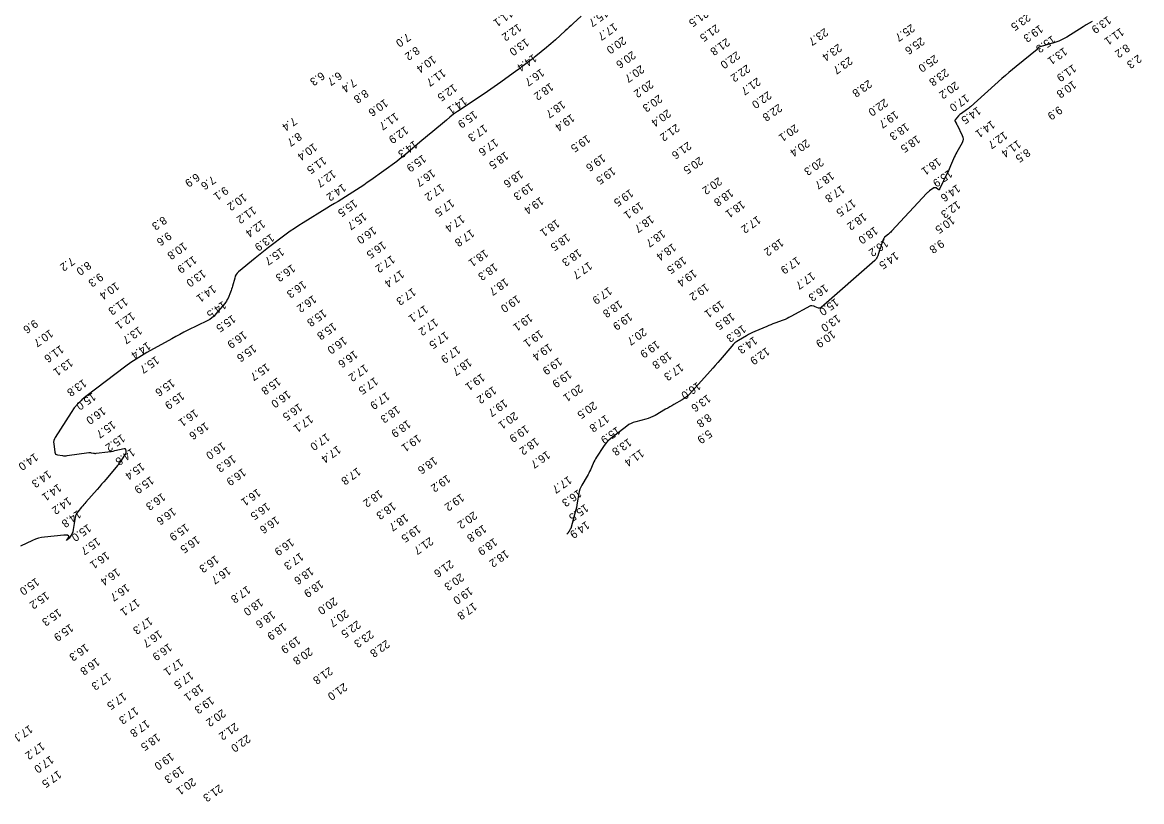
# Model space of a CAD drawing. Extents: x 988130 to 1132882, y 654656 to 841453.
# Drawn here: x 1035801 to 1036500, y 779520 to 780006 of the extents above; entities that cross this region are included whole.
import ezdxf

# ---------------------------------------------------------------- set-up
doc = ezdxf.new("R2010")
doc.units = 0
doc.layers.add('V-TOPO-MAJR', color=7, linetype='Continuous')
doc.layers.add('V-TOPO-SOUN', color=7, linetype='Continuous')

msp = doc.modelspace()

# ---------------------------------------------------------------- linework, layer by layer
at = {"layer": 'V-TOPO-MAJR'}
for points in [[(1036149.85, 780010.24), (1036144.84, 780005.7), (1036143.59, 780004.56), (1036142.34, 780003.42), (1036141.09, 780002.28), (1036139.85, 780001.14), (1036133.83, 779995.59), (1036132.46, 779994.35), (1036131.07, 779993.13), (1036129.66, 779991.93), (1036128.24, 779990.75), (1036121.56, 779985.29), (1036120.59, 779984.52), (1036119.62, 779983.75), (1036118.65, 779983), (1036117.66, 779982.26), (1036113.7, 779979.31), (1036112.7, 779978.57), (1036111.71, 779977.84), (1036110.72, 779977.1), (1036109.72, 779976.37), (1036099.66, 779969), (1036097.64, 779967.54), (1036095.61, 779966.1), (1036093.56, 779964.69), (1036091.49, 779963.3), (1036074.93, 779952.33), (1036072.54, 779950.71), (1036070.21, 779949.02), (1036067.92, 779947.27), (1036065.68, 779945.45), (1036055.92, 779937.31), (1036054.16, 779935.83), (1036052.39, 779934.35), (1036050.63, 779932.86), (1036048.88, 779931.36), (1036041.87, 779925.36), (1036040.11, 779923.88), (1036038.31, 779922.43), (1036036.49, 779921.02), (1036034.64, 779919.65), (1036018.49, 779907.94), (1036016.27, 779906.36), (1036014.04, 779904.83), (1036011.77, 779903.33), (1036009.48, 779901.86), (1036000.28, 779896.09), (1035997.97, 779894.65), (1035995.67, 779893.22), (1035993.35, 779891.79), (1035991.04, 779890.37), (1035976.13, 779881.26), (1035973.43, 779879.56), (1035970.77, 779877.8), (1035968.16, 779875.99), (1035965.58, 779874.11), (1035954.48, 779865.82), (1035952.37, 779864.22), (1035950.28, 779862.6), (1035948.22, 779860.94), (1035946.18, 779859.26), (1035935.86, 779850.61), (1035935.01, 779849.8), (1035934.32, 779848.88), (1035933.79, 779847.87), (1035933.4, 779846.77), (1035932.07, 779841.79), (1035931.79, 779840.82), (1035931.48, 779839.85), (1035931.14, 779838.9), (1035930.76, 779837.96), (1035929.21, 779834.21), (1035928.79, 779833.29), (1035928.3, 779832.41), (1035927.75, 779831.58), (1035927.13, 779830.78), (1035921.66, 779824.32), (1035920.47, 779823.05), (1035919.18, 779821.93), (1035917.77, 779820.95), (1035916.26, 779820.11), (1035904.09, 779814.15), (1035901.55, 779812.88), (1035899.02, 779811.58), (1035896.51, 779810.24), (1035894.02, 779808.87), (1035878.49, 779800.19), (1035875.11, 779798.22), (1035871.8, 779796.15), (1035868.57, 779793.96), (1035865.41, 779791.67), (1035840.45, 779772.89), (1035837.8, 779770.71), (1035835.37, 779768.31), (1035833.17, 779765.71), (1035831.19, 779762.9), (1035821.2, 779747.29), (1035820.69, 779746.33), (1035820.36, 779745.32), (1035820.23, 779744.27), (1035820.28, 779743.19), (1035820.94, 779738.06), (1035821.12, 779737.38), (1035821.47, 779736.86), (1035821.99, 779736.51), (1035822.67, 779736.33), (1035825.73, 779735.92), (1035826.49, 779735.84), (1035827.25, 779735.81), (1035828.02, 779735.84), (1035828.78, 779735.92), (1035842.19, 779737.72), (1035842.57, 779737.76), (1035842.94, 779737.76), (1035843.32, 779737.74), (1035843.7, 779737.68), (1035845.21, 779737.37), (1035845.58, 779737.31), (1035845.96, 779737.28), (1035846.34, 779737.28), (1035846.72, 779737.31), (1035854.07, 779738.21), (1035855.18, 779738.35), (1035856.28, 779738.53), (1035857.38, 779738.74), (1035858.47, 779738.98), (1035864.37, 779740.33), (1035864.66, 779740.35), (1035864.89, 779740.28), (1035865.04, 779740.1), (1035865.13, 779739.82), (1035865.36, 779738.5), (1035865.39, 779738.17), (1035865.36, 779737.86), (1035865.27, 779737.56), (1035865.13, 779737.26), (1035862.44, 779732.79), (1035861.92, 779731.96), (1035861.36, 779731.15), (1035860.77, 779730.37), (1035860.16, 779729.61), (1035852.98, 779721.16), (1035851.6, 779719.55), (1035850.22, 779717.95), (1035848.83, 779716.35), (1035847.43, 779714.77), (1035840.3, 779706.73), (1035839.65, 779705.99), (1035839.01, 779705.25), (1035838.38, 779704.5), (1035837.75, 779703.74), (1035835.26, 779700.7), (1035834.7, 779699.91), (1035834.25, 779699.07), (1035833.92, 779698.18), (1035833.71, 779697.24), (1035832.53, 779689.8), (1035832.18, 779688.3), (1035831.61, 779686.89), (1035830.83, 779685.6), (1035829.84, 779684.41), (1035828.3, 779682.81), (1035829.6, 779684.47), (1035829.77, 779685.58), (1035828.8, 779686.14), (1035826.69, 779686.15), (1035814.48, 779684.93), (1035812.58, 779684.66), (1035810.72, 779684.23), (1035808.9, 779683.65), (1035807.13, 779682.91), (1035799.53, 779679.34)], [(1036469.38, 780006.98), (1036467.48, 780005.92), (1036465.61, 780004.82), (1036463.75, 780003.68), (1036453.43, 779997.23), (1036451.8, 779996.28), (1036450.11, 779995.45), (1036448.38, 779994.72), (1036446.59, 779994.12), (1036436, 779990.89), (1036435.87, 779990.84), (1036435.75, 779990.76), (1036435.66, 779990.66), (1036435.59, 779990.54), (1036435.32, 779990.02), (1036435.25, 779989.89), (1036435.17, 779989.77), (1036435.07, 779989.66), (1036434.96, 779989.57), (1036421.71, 779978.8), (1036419.48, 779976.96), (1036417.27, 779975.1), (1036415.08, 779973.2), (1036412.91, 779971.29), (1036393.35, 779953.79), (1036392.72, 779953.25), (1036392.08, 779952.72), (1036391.41, 779952.22), (1036390.73, 779951.74), (1036387.63, 779949.62), (1036387.13, 779949.25), (1036386.65, 779948.85), (1036386.2, 779948.43), (1036385.78, 779947.97), (1036383.74, 779945.61), (1036383.57, 779945.36), (1036383.5, 779945.11), (1036383.53, 779944.85), (1036383.64, 779944.58), (1036384.28, 779943.48), (1036384.44, 779943.2), (1036384.59, 779942.92), (1036384.74, 779942.64), (1036384.88, 779942.36), (1036388.11, 779935.86), (1036388.54, 779934.69), (1036388.66, 779933.53), (1036388.48, 779932.37), (1036387.98, 779931.22), (1036384.71, 779925.44), (1036384.15, 779924.41), (1036383.62, 779923.36), (1036383.12, 779922.31), (1036382.66, 779921.23), (1036380.85, 779916.91), (1036380.39, 779915.83), (1036379.92, 779914.76), (1036379.43, 779913.69), (1036378.93, 779912.63), (1036373.95, 779902.25), (1036373.79, 779902.01), (1036373.6, 779901.9), (1036373.38, 779901.91), (1036373.13, 779902.03), (1036371.74, 779903.01), (1036371.63, 779903.07), (1036371.52, 779903.12), (1036371.4, 779903.15), (1036371.28, 779903.16), (1036370.77, 779903.17), (1036370.64, 779903.17), (1036370.52, 779903.14), (1036370.41, 779903.1), (1036370.3, 779903.03), (1036367.63, 779901.2), (1036367.16, 779900.86), (1036366.71, 779900.49), (1036366.29, 779900.1), (1036365.88, 779899.69), (1036343.8, 779875.98), (1036343.36, 779875.52), (1036342.91, 779875.08), (1036342.45, 779874.66), (1036341.97, 779874.25), (1036340.04, 779872.63), (1036339.59, 779872.2), (1036339.21, 779871.73), (1036338.89, 779871.2), (1036338.64, 779870.64), (1036337.43, 779867.27), (1036337.16, 779866.51), (1036336.9, 779865.74), (1036336.65, 779864.98), (1036336.4, 779864.21), (1036335.31, 779860.69), (1036334.99, 779859.87), (1036334.58, 779859.13), (1036334.07, 779858.45), (1036333.45, 779857.83), (1036299.96, 779828.32), (1036299.59, 779828.07), (1036299.2, 779827.93), (1036298.78, 779827.92), (1036298.35, 779828.04), (1036296.14, 779828.89), (1036295.9, 779828.98), (1036295.66, 779829.06), (1036295.42, 779829.13), (1036295.17, 779829.2), (1036294.18, 779829.45), (1036293.94, 779829.49), (1036293.7, 779829.48), (1036293.47, 779829.43), (1036293.24, 779829.33), (1036281, 779822.7), (1036279.8, 779822.08), (1036278.58, 779821.5), (1036277.35, 779820.96), (1036276.09, 779820.46), (1036271.02, 779818.56), (1036269.75, 779818.08), (1036268.49, 779817.58), (1036267.24, 779817.07), (1036265.99, 779816.55), (1036258.39, 779813.29), (1036257.08, 779812.71), (1036255.8, 779812.08), (1036254.53, 779811.42), (1036253.28, 779810.72), (1036248.33, 779807.84), (1036247.13, 779807.07), (1036246.01, 779806.21), (1036244.97, 779805.26), (1036244, 779804.21), (1036236.8, 779795.72), (1036235.28, 779793.95), (1036233.75, 779792.19), (1036232.2, 779790.44), (1036230.64, 779788.71), (1036217.61, 779774.35), (1036216.58, 779773.3), (1036215.47, 779772.34), (1036214.29, 779771.47), (1036213.04, 779770.69), (1036207.88, 779767.76), (1036206.59, 779767.03), (1036205.3, 779766.29), (1036204.01, 779765.55), (1036202.73, 779764.81), (1036196.15, 779761.02), (1036194.74, 779760.27), (1036193.29, 779759.62), (1036191.8, 779759.08), (1036190.27, 779758.63), (1036184.05, 779757.06), (1036182.53, 779756.59), (1036181.08, 779755.98), (1036179.71, 779755.21), (1036178.41, 779754.3), (1036168.45, 779746.52), (1036167.16, 779745.42), (1036165.96, 779744.23), (1036164.88, 779742.94), (1036163.89, 779741.56), (1036159.49, 779734.82), (1036158.91, 779733.89), (1036158.37, 779732.94), (1036157.87, 779731.96), (1036157.42, 779730.96), (1036155.67, 779726.93), (1036155.21, 779725.93), (1036154.73, 779724.95), (1036154.21, 779723.98), (1036153.66, 779723.03), (1036150.35, 779717.47), (1036149.68, 779716.21), (1036149.13, 779714.9), (1036148.71, 779713.54), (1036148.43, 779712.14), (1036147.52, 779706.3), (1036147.27, 779704.86), (1036146.98, 779703.42), (1036146.64, 779702), (1036146.26, 779700.58), (1036143.38, 779690.44), (1036143.36, 779690.39), (1036143.34, 779690.34), (1036143.31, 779690.29), (1036143.28, 779690.25), (1036143.16, 779690.06), (1036143.13, 779690.02), (1036143.1, 779689.97), (1036143.07, 779689.92), (1036143.04, 779689.88), (1036142.12, 779688.34), (1036142.02, 779688.18), (1036141.92, 779688.02), (1036141.81, 779687.86), (1036141.7, 779687.71), (1036141.02, 779686.81)]]:
    msp.add_lwpolyline(points, dxfattribs=at)

# ---------------------------------------------------------------- texts
at = {"layer": 'V-TOPO-SOUN'}
for s, p in [('11.1 ', (1036105.2, 780014.76)), ('15.7 ', (1036164.73, 780014.81)), ('21.5 ', (1036227.36, 780014.72)), ('23.5 ', (1036428.64, 780012.32)), ('13.9 ', (1036479.03, 780010.63)), ('12.2 ', (1036110.48, 780005.91)), ('17.7 ', (1036170.43, 780006.32)), ('21.5 ', (1036234.21, 780005.47)), ('23.7 ', (1036302.11, 780003.08)), ('25.7 ', (1036356.25, 780005.64)), ('19.3 ', (1036436.49, 780005.12)), ('11.1 ', (1036487.05, 780003.29)), ('7.0', (1036041.2, 779999.98)), ('13.0 ', (1036115.23, 779996.71)), ('20.0 ', (1036175.94, 779997.87)), ('21.8 ', (1036240.7, 779996.83)), ('23.4 ', (1036310.69, 779993.33)), ('25.6 ', (1036362.42, 779997.43)), ('15.3 ', (1036444.28, 779998.51)), ('8.2', (1036046.81, 779991.68)), ('14.4 ', (1036120.04, 779986.89)), ('20.6 ', (1036181.87, 779988.78)), ('22.0 ', (1036247.08, 779988.59)), ('25.0 ', (1036370.8, 779986.43)), ('13.1 ', (1036451.59, 779991.06)), ('8.2', (1036490.61, 779993.26)), ('2.3', (1036498.04, 779986.54)), ('10.4 ', (1036057.13, 779985.97)), ('20.7 ', (1036187.23, 779980.01)), ('22.2 ', (1036253.48, 779980.33)), ('23.7 ', (1036317.38, 779985.24)), ('11.9 ', (1036457.23, 779980.48)), ('6.3', (1035987.52, 779975.85)), ('6.7', (1035998.29, 779975.92)), ('11.7 ', (1036063.19, 779977.58)), ('16.7 ', (1036124.77, 779977.81)), ('23.8 ', (1036377.5, 779977.78)), ('7.4', (1036007.32, 779971.62)), ('12.5 ', (1036070.22, 779968.24)), ('18.2 ', (1036130.52, 779968.91)), ('20.2 ', (1036192.98, 779970.54)), ('21.7 ', (1036259.94, 779972.18)), ('23.8 ', (1036329.5, 779970.81)), ('20.2 ', (1036383.8, 779969.74)), ('10.8 ', (1036457.21, 779970.28)), ('8.8', (1036014.88, 779964.88)), ('10.6 ', (1036027.09, 779958.82)), ('14.1 ', (1036076.41, 779960.14)), ('20.3 ', (1036198.51, 779961.52)), ('22.0 ', (1036266.73, 779963.7)), ('22.0 ', (1036339.51, 779958.99)), ('17.0 ', (1036390.31, 779961.82)), ('15.9 ', (1036082.94, 779951.53)), ('18.7 ', (1036137.94, 779957.81)), ('20.4 ', (1036203.87, 779952.34)), ('22.8 ', (1036273.39, 779955.79)), ('19.7 ', (1036346.1, 779951.45)), ('14.5 ', (1036397.62, 779954.05)), ('9.9', (1036448.49, 779954.45)), ('7.4', (1035970.12, 779947.53)), ('11.7 ', (1036033.74, 779950.32)), ('19.4 ', (1036143.75, 779949.47)), ('14.1 ', (1036406.42, 779945.45)), ('8.7', (1035973.14, 779937.94)), ('12.9 ', (1036039.79, 779941.85)), ('17.3 ', (1036089.32, 779943.01)), ('21.2 ', (1036209.34, 779943.3)), ('20.1 ', (1036283.56, 779943.06)), ('18.3 ', (1036352.79, 779943.89)), ('12.7 ', (1036414.26, 779938.6)), ('10.4 ', (1035982.75, 779931.26)), ('14.3 ', (1036045.61, 779932.9)), ('17.6 ', (1036095.97, 779934.14)), ('19.5 ', (1036153.54, 779936.41)), ('21.6 ', (1036216.67, 779932.12)), ('20.4 ', (1036290.6, 779933.66)), ('18.5 ', (1036359.7, 779936.17)), ('11.4 ', (1036422.69, 779933.18)), ('15.9 ', (1036050.91, 779924.1)), ('18.5 ', (1036102.45, 779925.92)), ('19.6 ', (1036163.06, 779924.38)), ('8.5', (1036428.5, 779927.89)), ('11.5 ', (1035988.62, 779922.84)), ('20.5 ', (1036223.94, 779922.76)), ('20.3 ', (1036299.39, 779921.93)), ('18.1 ', (1036372.72, 779922.12)), ('6.9', (1035909.38, 779912.55)), ('7.6', (1035919.38, 779910.83)), ('12.7 ', (1035994.54, 779914.54)), ('16.7 ', (1036056.63, 779914.98)), ('18.6 ', (1036111.61, 779914.26)), ('19.5 ', (1036169.36, 779916.3)), ('20.2 ', (1036235.78, 779910.01)), ('18.7 ', (1036305.96, 779913.39)), ('15.9 ', (1036379.82, 779914.72)), ('9.1', (1035927.28, 779904.17)), ('14.2 ', (1036000.87, 779905.96)), ('17.2 ', (1036062.3, 779905.95)), ('19.3 ', (1036117.81, 779906.38)), ('19.5 ', (1036180.44, 779902.55)), ('18.8 ', (1036243.01, 779902.65)), ('17.8 ', (1036312.5, 779904.99)), ('14.6 ', (1036384.74, 779905.52)), ('10.2 ', (1035938.84, 779899.93)), ('15.5 ', (1036007.96, 779896.11)), ('17.5 ', (1036068.56, 779896.29)), ('19.4 ', (1036124.4, 779897.66)), ('17.5 ', (1036319.46, 779896.23)), ('11.2 ', (1035944.7, 779891.81)), ('19.1 ', (1036186.72, 779894.64)), ('18.1 ', (1036250.2, 779895.43)), ('12.3 ', (1036384.9, 779895.22)), ('8.3', (1035888.77, 779885.65)), ('12.4 ', (1035950.36, 779883.36)), ('15.7 ', (1036013.82, 779887.96)), ('17.4 ', (1036075.07, 779886.37)), ('18.1 ', (1036134.38, 779883.62)), ('18.7 ', (1036193.32, 779886.22)), ('17.2 ', (1036260.05, 779885.85)), ('18.2 ', (1036326.24, 779887.74)), ('10.5 ', (1036381.33, 779885.61)), ('9.6', (1035891.73, 779875.85)), ('13.9 ', (1035956.01, 779874.7)), ('16.0 ', (1036019.85, 779879.17)), ('17.8 ', (1036081.07, 779877.5)), ('18.5 ', (1036140.9, 779874.79)), ('18.7 ', (1036200.46, 779877.14)), ('18.0 ', (1036333.28, 779879.17)), ('10.8 ', (1035901.46, 779869.39)), ('16.5 ', (1036025.92, 779870.02)), ('18.4 ', (1036207.13, 779868.69)), ('18.2 ', (1036274.37, 779871.65)), ('16.2 ', (1036339.8, 779871.3)), ('9.8', (1036374.64, 779871.06)), ('11.9 ', (1035907.54, 779860.85)), ('15.7 ', (1035962.21, 779865.94)), ('17.2 ', (1036031.42, 779861.19)), ('18.1 ', (1036089.69, 779864.89)), ('18.3 ', (1036148.11, 779865.21)), ('14.5 ', (1036346.23, 779863.35)), ('7.2', (1035831.29, 779860.01)), ('8.0', (1035841.54, 779857.43)), ('16.3 ', (1035969.14, 779855.59)), ('18.3 ', (1036095.66, 779856.33)), ('17.7 ', (1036154.68, 779857.2)), ('18.5 ', (1036213.65, 779860.44)), ('17.9 ', (1036284.7, 779860.38)), ('9.3', (1035849.06, 779850.19)), ('13.0 ', (1035913.28, 779852.3)), ('17.4 ', (1036037.17, 779851.97)), ('18.7 ', (1036102.47, 779847)), ('19.4 ', (1036220.08, 779852.39)), ('17.7 ', (1036294.01, 779850.79)), ('10.4 ', (1035859.06, 779844.44)), ('14.1 ', (1035919.63, 779842.69)), ('16.3 ', (1035976.07, 779845.38)), ('17.3 ', (1036044.54, 779840.87)), ('17.9 ', (1036167.07, 779841.48)), ('19.2 ', (1036227.72, 779843.7)), ('16.3 ', (1036302.15, 779843.21)), ('11.3 ', (1035864.55, 779834.77)), ('14.5 ', (1035926.02, 779832.65)), ('16.2 ', (1035982.37, 779836.34)), ('19.0 ', (1036109.78, 779836.35)), ('18.8 ', (1036173.59, 779833.16)), ('19.1 ', (1036237.12, 779832.97)), ('15.0 ', (1036308.8, 779834.38)), ('12.1 ', (1035868.97, 779825.79)), ('15.8 ', (1035988.74, 779827.52)), ('17.1 ', (1036052.16, 779830.06)), ('9.6', (1035808.29, 779821.09)), ('15.5 ', (1035931.9, 779824.02)), ('15.8 ', (1035994.96, 779819.23)), ('17.2 ', (1036058.42, 779821.85)), ('19.1 ', (1036117.54, 779824.61)), ('19.9 ', (1036179.84, 779825.29)), ('18.5 ', (1036243.83, 779825.41)), ('13.0 ', (1036309.95, 779824.3)), ('10.7 ', (1035817.84, 779814.89)), ('13.7 ', (1035873.42, 779816.71)), ('16.9 ', (1035938.9, 779813.93)), ('17.5 ', (1036065.05, 779813.63)), ('19.1 ', (1036124.04, 779814.62)), ('20.7 ', (1036188.71, 779815.9)), ('16.3 ', (1036250.84, 779817.76)), ('10.9 ', (1036306.72, 779814.35)), ('11.6 ', (1035824.48, 779805.07)), ('14.4 ', (1035878.77, 779807.14)), ('15.6 ', (1035944.86, 779805.49)), ('16.0 ', (1036001.43, 779810.4)), ('17.9 ', (1036072.36, 779804.62)), ('19.4 ', (1036129.7, 779806.21)), ('19.9 ', (1036196.89, 779807.95)), ('14.3 ', (1036257.88, 779810.57)), ('15.7 ', (1035884.08, 779798.3)), ('16.6 ', (1036008.19, 779801.8)), ('18.8 ', (1036204.45, 779801.08)), ('12.9 ', (1036265.62, 779803.7)), ('13.1 ', (1035830.19, 779796.69)), ('15.7 ', (1035953.18, 779793.79)), ('17.2 ', (1036014.67, 779793.21)), ('18.7 ', (1036079.49, 779796.88)), ('19.9 ', (1036135.91, 779797.43)), ('17.3 ', (1036211.83, 779793.73)), ('13.8 ', (1035838.74, 779783.88)), ('15.6 ', (1035893.87, 779783.95)), ('15.8 ', (1035960.12, 779784.9)), ('17.5 ', (1036020.86, 779785.1)), ('19.1 ', (1036087.65, 779787.47)), ('19.9 ', (1036141.97, 779789.34)), ('16.0 ', (1035966.33, 779776.81)), ('19.2 ', (1036094.85, 779779.42)), ('20.1 ', (1036148.84, 779780.59)), ('16.0 ', (1036222.57, 779782.11)), ('15.0 ', (1035844.48, 779775.42)), ('15.9 ', (1035899.87, 779775.87)), ('17.9 ', (1036028.15, 779775.76)), ('19.7 ', (1036101.84, 779771.29)), ('20.5 ', (1036157.64, 779769.94)), ('13.6 ', (1036228.83, 779774.28)), ('16.0 ', (1035850.71, 779766.48)), ('16.1 ', (1035908.43, 779765.09)), ('16.5 ', (1035973.51, 779768.78)), ('18.3 ', (1036034.65, 779767.3)), ('20.1 ', (1036108.25, 779763.48)), ('15.7 ', (1035856.94, 779757.86)), ('16.6 ', (1035915.08, 779756.96)), ('17.1 ', (1035980.29, 779761.41)), ('18.9 ', (1036041.32, 779758.32)), ('17.8 ', (1036165.22, 779761.62)), ('8.8', (1036229.18, 779762.39)), ('15.2 ', (1035862.74, 779749.54)), ('17.0 ', (1035990.72, 779750.12)), ('19.1 ', (1036047.78, 779749.36)), ('19.9 ', (1036115.21, 779755.23)), ('15.9 ', (1036172.28, 779754.26)), ('5.9', (1036229.58, 779752.27)), ('16.0 ', (1035925.59, 779744.53)), ('17.4 ', (1035997.63, 779742.39)), ('18.2 ', (1036121.48, 779747.39)), ('13.8 ', (1036179.37, 779746.91)), ('14.0 ', (1035808.39, 779737.71)), ('14.8 ', (1035868.96, 779740.79)), ('16.3 ', (1035932.06, 779736.54)), ('18.6 ', (1036057.92, 779735.42)), ('16.7 ', (1036128.45, 779739.07)), ('11.4 ', (1036187.1, 779740.14)), ('15.4 ', (1035875.04, 779731.81)), ('16.9 ', (1035938.34, 779728.21)), ('17.8 ', (1036010.08, 779728.67)), ('14.3 ', (1035816.69, 779726.94)), ('15.9 ', (1035880.79, 779723.19)), ('19.2 ', (1036066.12, 779724.2)), ('17.7 ', (1036141.93, 779723.38)), ('14.1 ', (1035823.03, 779718.58)), ('16.1 ', (1035947.54, 779715.48)), ('18.2 ', (1036023.82, 779714.74)), ('16.3 ', (1036148.08, 779715.02)), ('14.2 ', (1035829.31, 779710.25)), ('16.3 ', (1035888.01, 779712.78)), ('16.5 ', (1035953.4, 779706.78)), ('18.3 ', (1036032.06, 779707.04)), ('19.2 ', (1036074.74, 779712.38)), ('14.8 ', (1035835.31, 779702.02)), ('16.6 ', (1035894.63, 779703.65)), ('18.7 ', (1036039.93, 779699.82)), ('20.2 ', (1036082.76, 779701.27)), ('15.5 ', (1036152.39, 779705.92)), ('15.0 ', (1035841.6, 779693.37)), ('15.9 ', (1035902.74, 779693.73)), ('16.6 ', (1035959.18, 779698.26)), ('19.5 ', (1036047.64, 779692.74)), ('19.8 ', (1036088.65, 779692.95)), ('14.9 ', (1036153.01, 779695.25)), ('16.5 ', (1035909.54, 779686)), ('15.7 ', (1035847.31, 779684.99)), ('16.9 ', (1035968.39, 779684.47)), ('21.7 ', (1036055.4, 779685.22)), ('18.9 ', (1036095.42, 779684.68)), ('16.1 ', (1035853.06, 779676.21)), ('16.3 ', (1035921.37, 779673.83)), ('17.3 ', (1035974.32, 779675.56)), ('18.2 ', (1036102.64, 779677.23)), ('16.4 ', (1035859.66, 779665.79)), ('16.7 ', (1035928.82, 779666.73)), ('18.6 ', (1035980.67, 779666.44)), ('21.6 ', (1036068.06, 779670.91)), ('15.0 ', (1035809.15, 779659.81)), ('18.9 ', (1035986.77, 779658.39)), ('20.3 ', (1036074.57, 779662.64)), ('15.2 ', (1035815.38, 779651.16)), ('16.7 ', (1035865.66, 779656.04)), ('17.8 ', (1035941.12, 779654.82)), ('19.0 ', (1036080.05, 779654.07)), ('17.1 ', (1035871.98, 779646.69)), ('18.0 ', (1035949.07, 779646.96)), ('20.0 ', (1035995.47, 779647.67)), ('17.8 ', (1036082.63, 779644.4)), ('15.3 ', (1035823.09, 779640.54)), ('18.6 ', (1035956.67, 779639.18)), ('20.7 ', (1036002.5, 779639.95)), ('15.9 ', (1035830.49, 779631.02)), ('17.3 ', (1035879.98, 779635.29)), ('18.9 ', (1035963.8, 779631.7)), ('22.5 ', (1036010.01, 779633.13)), ('16.7 ', (1035885.99, 779627.18)), ('19.9 ', (1035972.42, 779623.29)), ('23.3 ', (1036018.12, 779627.02)), ('16.3 ', (1035840.13, 779618.66)), ('16.9 ', (1035892.11, 779618.91)), ('20.8 ', (1035979.97, 779616.32)), ('22.8 ', (1036028.14, 779621.01)), ('16.8 ', (1035846.96, 779609.82)), ('17.1 ', (1035899.19, 779609.39)), ('21.8 ', (1035992.49, 779604.1)), ('17.3 ', (1035854.02, 779600.47)), ('17.5 ', (1035905.58, 779601.27)), ('17.5 ', (1035863.68, 779588.23)), ('18.1 ', (1035911.88, 779593.45)), ('21.0 ', (1036001.64, 779594.14)), ('19.3 ', (1035918.41, 779585.69)), ('17.3 ', (1035871.19, 779579.21)), ('20.2 ', (1035925.65, 779577.75)), ('17.1 ', (1035805.04, 779567.85)), ('17.8 ', (1035878.16, 779571.12)), ('21.2 ', (1035933.62, 779569.29)), ('18.5 ', (1035884.8, 779562.63)), ('22.0 ', (1035941.18, 779561.8)), ('17.2 ', (1035812.59, 779557.13)), ('17.0 ', (1035818.17, 779548.74)), ('19.0 ', (1035893.34, 779550.58)), ('17.5 ', (1035823, 779539.53)), ('19.3 ', (1035899.63, 779542.26)), ('20.1 ', (1035907.01, 779534.92)), ('21.3 ', (1035923.8, 779530.74))]:
    msp.add_text(s, height=5, rotation=215, dxfattribs=at).set_placement(p)

doc.saveas('drawing.dxf')
